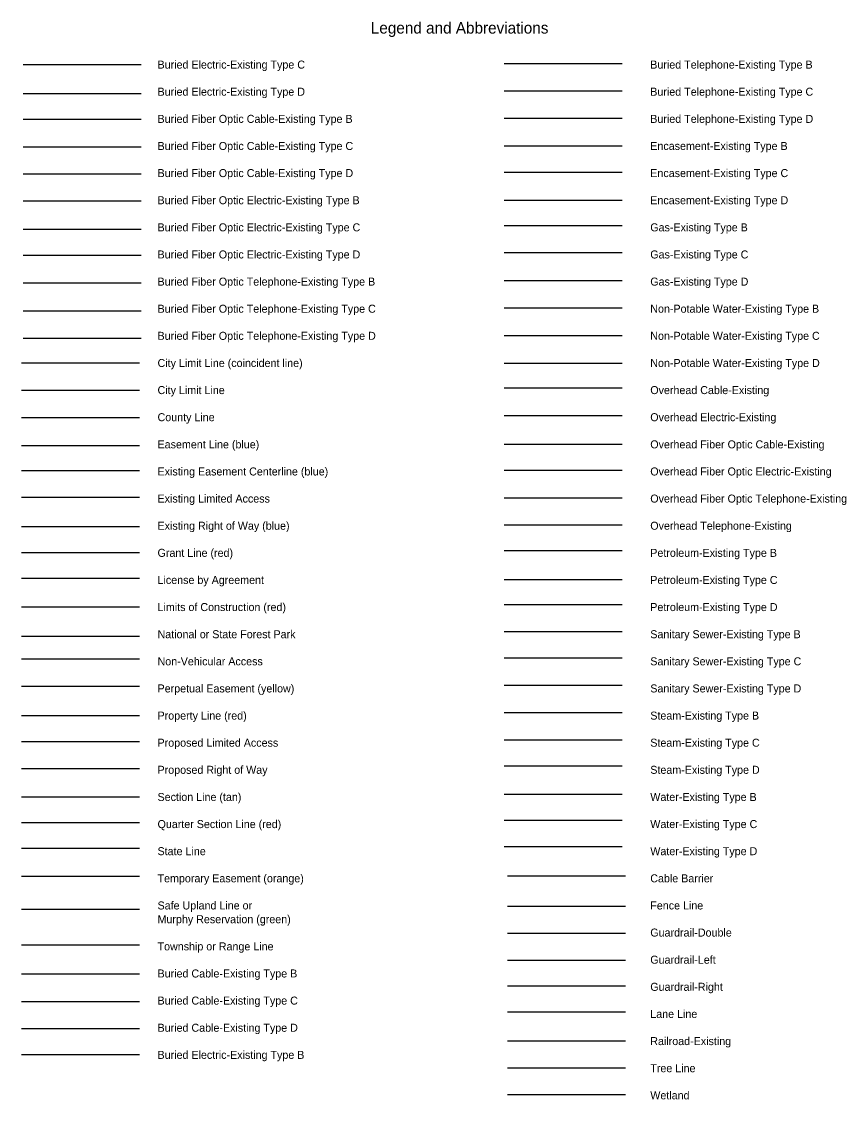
# Model space of a CAD drawing. Extents: x -371 to 730, y -9 to 425.
# Drawn here: x 270.7 to 451.1, y 188.8 to 424.6 of the extents above; entities that cross this region are included whole.
import ezdxf

# ---------------------------------------------------------------- set-up
doc = ezdxf.new("R2010")
doc.units = 0

msp = doc.modelspace()

# ---------------------------------------------------------------- linework, layer by layer
for p, q in [((271.03, 415.2), (296.83, 415.2)), ((376.21, 415.44), (402.01, 415.44)), ((271.03, 408.82), (296.83, 408.82)), ((376.21, 409.42), (402.01, 409.42)), ((271.03, 403.25), (296.83, 403.25)), ((376.21, 403.49), (402.01, 403.49)), ((271.03, 397.17), (296.83, 397.17)), ((376.21, 397.37), (402.01, 397.37)), ((376.21, 391.62), (402.01, 391.62)), ((271.03, 391.31), (296.83, 391.31)), ((271.03, 385.38), (296.83, 385.38)), ((376.21, 385.51), (402.01, 385.51)), ((376.21, 379.97), (402.01, 379.97)), ((271.03, 379.19), (296.83, 379.19)), ((271.03, 373.52), (296.83, 373.52)), ((376.21, 374.07), (402.01, 374.07)), ((376.21, 367.96), (402.01, 367.96)), ((271.03, 367.47), (296.83, 367.47)), ((271.03, 361.34), (296.83, 361.34)), ((376.21, 361.99), (402.01, 361.99)), ((271.03, 355.3), (296.83, 355.3)), ((376.21, 355.91), (402.01, 355.91)), ((270.65, 349.91), (296.45, 349.91)), ((376.21, 349.83), (402.01, 349.83)), ((376.21, 344.48), (402.01, 344.48)), ((270.65, 343.95), (296.45, 343.95)), ((270.65, 337.95), (296.45, 337.95)), ((376.21, 338.4), (402.01, 338.4)), ((270.65, 331.86), (296.45, 331.86)), ((376.21, 332.13), (402.01, 332.13)), ((270.65, 326.4), (296.45, 326.4)), ((376.21, 326.45), (402.01, 326.45)), ((270.65, 320.59), (296.45, 320.59)), ((376.21, 320.44), (402.01, 320.44)), ((270.65, 314.14), (296.45, 314.14)), ((376.21, 314.49), (402.01, 314.49)), ((376.21, 308.89), (402.01, 308.89)), ((270.65, 308.44), (296.45, 308.44)), ((270.65, 302.84), (296.45, 302.84)), ((376.21, 302.57), (402.01, 302.57)), ((270.65, 296.56), (296.45, 296.56)), ((376.21, 297.05), (402.01, 297.05)), ((270.65, 290.18), (296.45, 290.18)), ((376.21, 291.16), (402.01, 291.16)), ((376.21, 285.43), (402.01, 285.43)), ((270.65, 285.22), (296.45, 285.22)), ((270.65, 279.18), (296.45, 279.18)), ((376.21, 279.43), (402.01, 279.43)), ((270.65, 272.81), (296.45, 272.81)), ((376.21, 273.42), (402.01, 273.42)), ((270.65, 267.1), (296.45, 267.1)), ((376.21, 267.46), (402.01, 267.46)), ((376.21, 261.79), (402.01, 261.79)), ((270.65, 261.2), (296.45, 261.2)), ((270.65, 254.99), (296.45, 254.99)), ((376.21, 255.58), (402.01, 255.58)), ((270.65, 249.42), (296.45, 249.42)), ((376.21, 249.89), (402.01, 249.89)), ((270.65, 243.78), (296.45, 243.78)), ((376.21, 244.16), (402.01, 244.16)), ((270.65, 237.65), (296.45, 237.65)), ((376.94, 237.7), (402.74, 237.7)), ((376.94, 231.09), (402.74, 231.09)), ((270.65, 230.42), (296.45, 230.42)), ((376.94, 225.21), (402.74, 225.21)), ((270.66, 222.65), (296.46, 222.65)), ((376.94, 219.28), (402.74, 219.28)), ((270.66, 216.27), (296.46, 216.27)), ((376.94, 213.66), (402.74, 213.66)), ((270.66, 210.23), (296.46, 210.23)), ((376.94, 207.95), (402.74, 207.95)), ((270.66, 204.33), (296.46, 204.33)), ((376.94, 201.66), (402.74, 201.66)), ((270.66, 198.63), (296.46, 198.63)), ((376.94, 195.7), (402.74, 195.7)), ((376.94, 189.87), (402.74, 189.87))]:
    msp.add_line(p, q)

# ---------------------------------------------------------------- texts
for s, height, p in [('Legend and Abbreviations', 2.5, (347.05, 421.96)), ('Buried Electric-Existing Type C', 1.75, (300.4, 414.3)), ('Buried Telephone-Existing Type B', 1.75, (408.18, 414.3)), ('Buried Electric-Existing Type D', 1.75, (300.4, 408.37)), ('Buried Telephone-Existing Type C', 1.75, (408.18, 408.37)), ('Buried Fiber Optic Cable-Existing Type B', 1.75, (300.4, 402.43)), ('Buried Telephone-Existing Type D', 1.75, (408.18, 402.43)), ('Buried Fiber Optic Cable-Existing Type C', 1.75, (300.4, 396.5)), ('Encasement-Existing Type B', 1.75, (408.18, 396.5)), ('Buried Fiber Optic Cable-Existing Type D', 1.75, (300.4, 390.57)), ('Encasement-Existing Type C', 1.75, (408.18, 390.57)), ('Buried Fiber Optic Electric-Existing Type B', 1.75, (300.4, 384.63)), ('Encasement-Existing Type D', 1.75, (408.18, 384.63)), ('Buried Fiber Optic Electric-Existing Type C', 1.75, (300.4, 378.7)), ('Gas-Existing Type B', 1.75, (408.18, 378.7)), ('Buried Fiber Optic Electric-Existing Type D', 1.75, (300.4, 372.77)), ('Gas-Existing Type C', 1.75, (408.18, 372.77)), ('Buried Fiber Optic Telephone-Existing Type B', 1.75, (300.4, 366.83)), ('Gas-Existing Type D', 1.75, (408.18, 366.83)), ('Buried Fiber Optic Telephone-Existing Type C', 1.75, (300.4, 360.9)), ('Non-Potable Water-Existing Type B', 1.75, (408.18, 360.9)), ('Buried Fiber Optic Telephone-Existing Type D', 1.75, (300.4, 354.97)), ('Non-Potable Water-Existing Type C', 1.75, (408.18, 354.97)), ('City Limit Line (coincident line)', 1.75, (300.4, 349.03)), ('Non-Potable Water-Existing Type D', 1.75, (408.18, 349.03)), ('City Limit Line', 1.75, (300.4, 343.1)), ('Overhead Cable-Existing', 1.75, (408.18, 343.1)), ('County Line', 1.75, (300.4, 337.17)), ('Overhead Electric-Existing', 1.75, (408.18, 337.17)), ('Easement Line (blue)', 1.75, (300.4, 331.23)), ('Overhead Fiber Optic Cable-Existing', 1.75, (408.18, 331.23)), ('Existing Easement Centerline (blue)', 1.75, (300.4, 325.3)), ('Overhead Fiber Optic Electric-Existing', 1.75, (408.18, 325.3)), ('Existing Limited Access', 1.75, (300.4, 319.37)), ('Overhead Fiber Optic Telephone-Existing', 1.75, (408.18, 319.37)), ('Existing Right of Way (blue)', 1.75, (300.4, 313.43)), ('Overhead Telephone-Existing', 1.75, (408.18, 313.43)), ('Grant Line (red)', 1.75, (300.4, 307.5)), ('Petroleum-Existing Type B', 1.75, (408.18, 307.5)), ('License by Agreement', 1.75, (300.4, 301.57)), ('Petroleum-Existing Type C', 1.75, (408.18, 301.57)), ('Limits of Construction (red)', 1.75, (300.4, 295.64)), ('Petroleum-Existing Type D', 1.75, (408.18, 295.64)), ('National or State Forest Park', 1.75, (300.4, 289.7)), ('Sanitary Sewer-Existing Type B', 1.75, (408.18, 289.7)), ('Non-Vehicular Access', 1.75, (300.4, 283.77)), ('Sanitary Sewer-Existing Type C', 1.75, (408.18, 283.77)), ('Perpetual Easement (yellow)', 1.75, (300.4, 277.84)), ('Sanitary Sewer-Existing Type D', 1.75, (408.18, 277.84)), ('Property Line (red)', 1.75, (300.4, 271.9)), ('Steam-Existing Type B', 1.75, (408.18, 271.9)), ('Proposed Limited Access', 1.75, (300.4, 265.97)), ('Steam-Existing Type C', 1.75, (408.18, 265.97)), ('Proposed Right of Way', 1.75, (300.4, 260.04)), ('Steam-Existing Type D', 1.75, (408.18, 260.04)), ('Section Line (tan)', 1.75, (300.4, 254.1)), ('Water-Existing Type B', 1.75, (408.18, 254.1)), ('Quarter Section Line (red)', 1.75, (300.4, 248.17)), ('Water-Existing Type C', 1.75, (408.18, 248.17)), ('State Line', 1.75, (300.4, 242.24)), ('Water-Existing Type D', 1.75, (408.18, 242.24)), ('Temporary Easement (orange)', 1.75, (300.4, 236.31)), ('Cable Barrier', 1.75, (408.18, 236.3)), ('Safe Upland Line or ', 1.75, (300.4, 230.37)), ('Fence Line', 1.75, (408.18, 230.37)), ('Murphy Reservation (green)', 1.75, (300.4, 227.36)), ('Guardrail-Double', 1.75, (408.18, 224.44)), ('Township or Range Line', 1.75, (300.4, 221.42)), ('Guardrail-Left', 1.75, (408.18, 218.5)), ('Buried Cable-Existing Type B', 1.75, (300.4, 215.49)), ('Guardrail-Right', 1.75, (408.18, 212.57)), ('Buried Cable-Existing Type C', 1.75, (300.4, 209.56)), ('Lane Line', 1.75, (408.18, 206.64)), ('Buried Cable-Existing Type D', 1.75, (300.4, 203.62)), ('Railroad-Existing', 1.75, (408.18, 200.7)), ('Buried Electric-Existing Type B', 1.75, (300.4, 197.69)), ('Tree Line', 1.75, (408.18, 194.77)), ('Wetland', 1.75, (408.18, 188.84))]:
    msp.add_text(s, height=height).set_placement(p)

doc.saveas('drawing.dxf')
